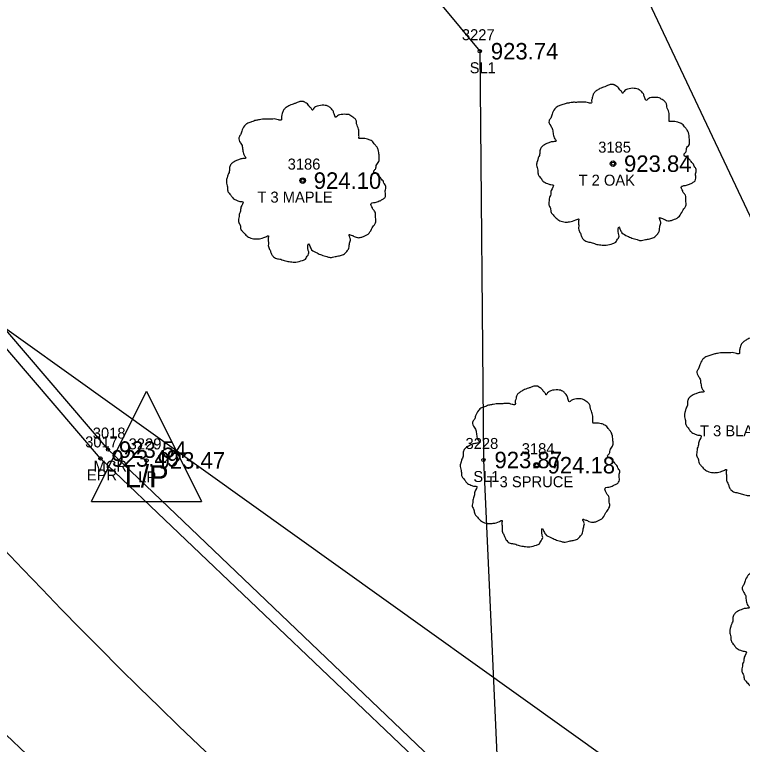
# Model space of a CAD drawing. Extents: x 1575382 to 1578175, y 1099175 to 1101955.
# Drawn here: x 1576931 to 1576997.2, y 1100870.5 to 1100936.8 of the extents above; entities that cross this region are included whole.
import ezdxf

# ---------------------------------------------------------------- set-up
doc = ezdxf.new("R2010")
doc.units = 0
for name, color, linetype in [('RD_EX_Conc', 7, 'Continuous'), ('RD_EX_Conc_txCode', 7, 'Continuous'), ('RD_EX_Road', 7, 'Continuous'), ('RD_EX_Road_txCode', 7, 'Continuous'), ('RD_EX_TX_Conc_ELEV', 7, 'Continuous'), ('RD_EX_TX_Road_ELEV', 7, 'Continuous'), ('RD_EX_TX_UT_ELEV', 7, 'Continuous'), ('RD_EX_TX_VEG_ELEV', 7, 'Continuous'), ('RD_EX_UT', 7, 'Continuous'), ('RD_EX_UT_txCode', 7, 'Continuous'), ('RD_EX_VEG', 7, 'Continuous'), ('RD_EX_VEG_txCode', 7, 'Continuous'), ('RD_HC_Cl', 7, 'Continuous'), ('RD_SMD_Locator', 7, 'Continuous')]:
    doc.layers.add(name, color=color, linetype=linetype)

msp = doc.modelspace()

# ---------------------------------------------------------------- linework, layer by layer
at = {"layer": 'RD_EX_Conc'}
msp.add_lwpolyline([(1577061.066, 1100806.234), (1577014.096, 1100833.352), (1576975.058, 1100863.303), (1576939.512, 1100897.242), (1576908.218, 1100933.822), (1576881.099, 1100974.578), (1576859.041, 1101017.292), (1576841.041, 1101063.527), (1576828.933, 1101110.765), (1576816.791, 1101158.901)], dxfattribs=at)
at = {"layer": 'RD_EX_Road'}
for points in [[(1577060.606, 1100805.432), (1577013.537, 1100832.507), (1576974.41, 1100862.521), (1576938.821, 1100896.441), (1576907.275, 1100933.28), (1576880.287, 1100973.975), (1576858.202, 1101016.828), (1576840.123, 1101063.131), (1576827.927, 1101110.583), (1576815.842, 1101158.489)], [(1576898.125, 1100449.597), (1576900.298, 1100453.323), (1576908.44, 1100470.191), (1576911.626, 1100476.811), (1576915.143, 1100482.86), (1576932.491, 1100514.031), (1576964.319, 1100571.231), (1576981.085, 1100601.291), (1577005.143, 1100644.548), (1577029.514, 1100688.699), (1577055.929, 1100735.941), (1577058.213, 1100744.654), (1577059.154, 1100754.07), (1577057.45, 1100760.722), (1577053.131, 1100767.877), (1577044.533, 1100776.687), (1577044.533, 1100776.687), (1577000.541, 1100813.123), (1576959.676, 1100843.401), (1576921.642, 1100879.474), (1576887.689, 1100919.798), (1576859.542, 1100961.835), (1576835.397, 1101008.919), (1576817.257, 1101055.711)]]:
    msp.add_lwpolyline(points, dxfattribs=at)
at = {"layer": 'RD_EX_UT'}
for p, q in [((1576938.018, 1100892.538), (1576943.018, 1100902.538)), ((1576943.018, 1100902.538), (1576948.018, 1100892.538)), ((1576938.018, 1100892.538), (1576948.018, 1100892.538))]:
    msp.add_line(p, q, dxfattribs=at)
msp.add_lwpolyline([(1576697.982, 1101074.318), (1577079.486, 1100801.524), (1576931.929, 1100529.296), (1577183.503, 1100413.666)], dxfattribs=at)
at = {"layer": 'RD_EX_VEG'}
for points in [[(1576842.661, 1101165.203), (1576856.324, 1101117.296), (1576901.07, 1101050.702), (1576926.345, 1101005.763), (1576957.585, 1100975.469), (1576985.787, 1100943.994), (1577005.951, 1100901.315), (1577049.501, 1100868.209), (1577075.374, 1100845.032), (1577056.225, 1100809.989)], [(1576823.907, 1101161.244), (1576835.181, 1101111.009), (1576847.368, 1101072.746), (1576888.665, 1101041.707), (1576913.762, 1100995.867), (1576945.147, 1100967.302), (1576973.299, 1100933.425), (1576973.63, 1100896.298), (1576975.024, 1100865.506), (1577014.084, 1100835.799), (1577056.225, 1100809.989)]]:
    msp.add_lwpolyline(points, dxfattribs=at)
for centre, radius in [((1576985.404, 1100923.212), 0.25), ((1576985.391, 1100923.193), 0.0001), ((1576957.207, 1100921.676), 0.25), ((1576957.195, 1100921.657), 0.0001), ((1576978.456, 1100895.823), 0.25), ((1576978.443, 1100895.804), 0.0001)]:
    msp.add_circle(centre, radius, dxfattribs=at)
for points in [[(1576985.536, 1100930.379), (1576985.236, 1100930.404), (1576984.911, 1100930.304), (1576984.661, 1100930.204), (1576984.436, 1100930.129), (1576984.212, 1100930.029), (1576983.912, 1100929.854), (1576983.687, 1100929.654), (1576983.562, 1100929.404), (1576983.512, 1100929.179), (1576983.462, 1100928.905), (1576983.462, 1100928.73), (1576983.337, 1100928.705), (1576983.187, 1100928.73), (1576982.937, 1100928.805), (1576982.687, 1100928.805), (1576982.437, 1100928.805), (1576982.087, 1100928.78), (1576981.738, 1100928.78), (1576981.463, 1100928.73), (1576981.138, 1100928.68), (1576980.763, 1100928.555), (1576980.413, 1100928.43), (1576980.113, 1100928.18), (1576979.863, 1100927.705), (1576979.738, 1100927.355), (1576979.589, 1100927.105), (1576979.738, 1100926.656), (1576979.913, 1100926.306), (1576979.938, 1100926.106), (1576980.013, 1100925.681), (1576980.113, 1100925.456), (1576980.238, 1100925.256), (1576980.163, 1100925.231), (1576979.788, 1100925.181), (1576979.489, 1100925.081), (1576979.064, 1100924.856), (1576978.839, 1100924.631), (1576978.739, 1100924.307), (1576978.714, 1100923.957), (1576978.614, 1100923.757), (1576978.539, 1100923.482), (1576978.514, 1100923.407), (1576978.464, 1100923.082), (1576978.564, 1100922.632), (1576978.589, 1100922.282), (1576978.714, 1100922.058), (1576978.864, 1100921.883), (1576979.039, 1100921.633), (1576979.439, 1100921.408), (1576979.763, 1100921.308), (1576979.963, 1100921.283), (1576979.788, 1100920.783), (1576979.738, 1100920.433), (1576979.614, 1100920.033), (1576979.614, 1100919.959), (1576979.564, 1100919.484), (1576979.713, 1100919.159), (1576979.788, 1100918.784), (1576979.963, 1100918.559), (1576980.238, 1100918.259), (1576980.563, 1100918.034), (1576981.063, 1100917.909), (1576981.463, 1100917.934), (1576982.038, 1100918.109), (1576982.287, 1100918.184), (1576982.262, 1100918.009), (1576982.287, 1100917.634), (1576982.287, 1100917.21), (1576982.437, 1100916.885), (1576982.537, 1100916.61), (1576982.687, 1100916.36), (1576983.012, 1100916.135), (1576983.412, 1100916.06), (1576983.837, 1100915.91), (1576984.287, 1100915.835), (1576984.786, 1100915.81), (1576985.386, 1100915.96), (1576985.661, 1100916.085), (1576985.761, 1100916.26), (1576985.961, 1100916.635), (1576985.911, 1100916.86), (1576985.936, 1100917.46), (1576986.036, 1100917.285), (1576986.211, 1100916.935), (1576986.71, 1100916.635), (1576987.11, 1100916.46), (1576987.585, 1100916.31), (1576987.885, 1100916.235), (1576988.36, 1100916.31), (1576988.735, 1100916.385), (1576989.109, 1100916.51), (1576989.409, 1100916.785), (1576989.584, 1100917.06), (1576989.634, 1100917.335), (1576989.709, 1100917.709), (1576989.759, 1100917.884)], [(1576989.759, 1100917.884), (1576989.684, 1100918.059), (1576989.634, 1100918.309), (1576989.709, 1100918.284), (1576989.884, 1100918.234), (1576990.159, 1100918.109), (1576990.384, 1100918.034), (1576990.709, 1100918.059), (1576990.984, 1100918.159), (1576991.433, 1100918.434), (1576991.708, 1100918.909), (1576991.983, 1100919.309), (1576992.058, 1100919.634), (1576992.008, 1100919.859), (1576991.983, 1100920.358), (1576991.783, 1100920.608), (1576991.733, 1100920.733), (1576991.633, 1100921.133), (1576991.708, 1100921.183), (1576991.983, 1100921.233), (1576992.358, 1100921.358), (1576992.633, 1100921.483), (1576992.858, 1100921.658), (1576992.933, 1100921.883), (1576992.908, 1100922.282), (1576992.958, 1100922.682), (1576992.883, 1100922.832), (1576992.783, 1100922.982), (1576992.708, 1100923.182), (1576992.558, 1100923.332), (1576992.458, 1100923.482), (1576992.358, 1100923.582), (1576992.233, 1100923.732), (1576992.058, 1100923.857), (1576991.908, 1100923.907), (1576991.858, 1100924.057), (1576992.008, 1100924.257), (1576992.058, 1100924.357), (1576992.083, 1100924.581), (1576992.308, 1100924.931), (1576992.358, 1100925.331), (1576992.308, 1100925.756), (1576992.258, 1100926.031), (1576992.108, 1100926.306), (1576991.908, 1100926.556), (1576991.783, 1100926.731), (1576991.608, 1100926.855), (1576991.283, 1100926.98), (1576991.034, 1100927.03), (1576990.684, 1100927.03), (1576990.484, 1100927.08), (1576990.509, 1100927.13), (1576990.509, 1100927.28), (1576990.509, 1100927.555), (1576990.434, 1100928.005), (1576990.284, 1100928.505), (1576990.284, 1100928.53), (1576990.184, 1100928.78), (1576989.959, 1100928.98), (1576989.784, 1100929.079), (1576989.584, 1100929.204), (1576989.334, 1100929.229), (1576989.034, 1100929.229), (1576988.76, 1100929.179), (1576988.56, 1100929.079), (1576988.385, 1100928.955), (1576988.31, 1100929.104), (1576988.21, 1100929.404), (1576988.16, 1100929.554), (1576988.01, 1100929.729), (1576987.785, 1100929.929), (1576987.335, 1100930.054), (1576986.71, 1100929.979), (1576986.411, 1100929.779), (1576986.261, 1100929.604), (1576986.211, 1100929.729), (1576986.011, 1100929.929), (1576985.911, 1100930.104), (1576985.736, 1100930.229), (1576985.586, 1100930.329), (1576985.486, 1100930.379)], [(1576957.339, 1100928.843), (1576957.039, 1100928.868), (1576956.714, 1100928.768), (1576956.464, 1100928.668), (1576956.24, 1100928.593), (1576956.015, 1100928.493), (1576955.715, 1100928.318), (1576955.49, 1100928.118), (1576955.365, 1100927.868), (1576955.315, 1100927.643), (1576955.265, 1100927.368), (1576955.265, 1100927.193), (1576955.14, 1100927.168), (1576954.99, 1100927.193), (1576954.74, 1100927.268), (1576954.49, 1100927.268), (1576954.24, 1100927.268), (1576953.891, 1100927.243), (1576953.541, 1100927.243), (1576953.266, 1100927.193), (1576952.941, 1100927.144), (1576952.566, 1100927.019), (1576952.216, 1100926.894), (1576951.916, 1100926.644), (1576951.667, 1100926.169), (1576951.542, 1100925.819), (1576951.392, 1100925.569), (1576951.542, 1100925.119), (1576951.717, 1100924.769), (1576951.741, 1100924.57), (1576951.816, 1100924.145), (1576951.916, 1100923.92), (1576952.041, 1100923.72), (1576951.966, 1100923.695), (1576951.592, 1100923.645), (1576951.292, 1100923.545), (1576950.867, 1100923.32), (1576950.642, 1100923.095), (1576950.542, 1100922.77), (1576950.517, 1100922.421), (1576950.417, 1100922.221), (1576950.342, 1100921.946), (1576950.317, 1100921.871), (1576950.267, 1100921.546), (1576950.367, 1100921.096), (1576950.392, 1100920.746), (1576950.517, 1100920.521), (1576950.667, 1100920.346), (1576950.842, 1100920.097), (1576951.242, 1100919.872), (1576951.567, 1100919.772), (1576951.766, 1100919.747), (1576951.592, 1100919.247), (1576951.542, 1100918.897), (1576951.417, 1100918.497), (1576951.417, 1100918.422), (1576951.367, 1100917.948), (1576951.517, 1100917.623), (1576951.592, 1100917.248), (1576951.766, 1100917.023), (1576952.041, 1100916.723), (1576952.366, 1100916.498), (1576952.866, 1100916.373), (1576953.266, 1100916.398), (1576953.841, 1100916.573), (1576954.09, 1100916.648), (1576954.065, 1100916.473), (1576954.09, 1100916.098), (1576954.09, 1100915.674), (1576954.24, 1100915.349), (1576954.34, 1100915.074), (1576954.49, 1100914.824), (1576954.815, 1100914.599), (1576955.215, 1100914.524), (1576955.64, 1100914.374), (1576956.09, 1100914.299), (1576956.589, 1100914.274), (1576957.189, 1100914.424), (1576957.464, 1100914.549), (1576957.564, 1100914.724), (1576957.764, 1100915.099), (1576957.714, 1100915.324), (1576957.739, 1100915.923), (1576957.839, 1100915.748), (1576958.014, 1100915.399), (1576958.514, 1100915.099), (1576958.913, 1100914.924), (1576959.388, 1100914.774), (1576959.688, 1100914.699), (1576960.163, 1100914.774), (1576960.538, 1100914.849), (1576960.912, 1100914.974), (1576961.212, 1100915.249), (1576961.387, 1100915.524), (1576961.437, 1100915.798), (1576961.512, 1100916.173), (1576961.562, 1100916.348)], [(1576961.562, 1100916.348), (1576961.487, 1100916.523), (1576961.437, 1100916.773), (1576961.512, 1100916.748), (1576961.687, 1100916.698), (1576961.962, 1100916.573), (1576962.187, 1100916.498), (1576962.512, 1100916.523), (1576962.787, 1100916.623), (1576963.236, 1100916.898), (1576963.511, 1100917.373), (1576963.786, 1100917.773), (1576963.861, 1100918.097), (1576963.811, 1100918.322), (1576963.786, 1100918.822), (1576963.586, 1100919.072), (1576963.536, 1100919.197), (1576963.436, 1100919.597), (1576963.511, 1100919.647), (1576963.786, 1100919.697), (1576964.161, 1100919.822), (1576964.436, 1100919.947), (1576964.661, 1100920.122), (1576964.736, 1100920.346), (1576964.711, 1100920.746), (1576964.761, 1100921.146), (1576964.686, 1100921.296), (1576964.586, 1100921.446), (1576964.511, 1100921.646), (1576964.361, 1100921.796), (1576964.261, 1100921.946), (1576964.161, 1100922.046), (1576964.036, 1100922.196), (1576963.861, 1100922.321), (1576963.711, 1100922.371), (1576963.661, 1100922.52), (1576963.811, 1100922.72), (1576963.861, 1100922.82), (1576963.886, 1100923.045), (1576964.111, 1100923.395), (1576964.161, 1100923.795), (1576964.111, 1100924.22), (1576964.061, 1100924.495), (1576963.911, 1100924.769), (1576963.711, 1100925.019), (1576963.586, 1100925.194), (1576963.411, 1100925.319), (1576963.087, 1100925.444), (1576962.837, 1100925.494), (1576962.487, 1100925.494), (1576962.287, 1100925.544), (1576962.312, 1100925.594), (1576962.312, 1100925.744), (1576962.312, 1100926.019), (1576962.237, 1100926.469), (1576962.087, 1100926.969), (1576962.087, 1100926.994), (1576961.987, 1100927.243), (1576961.762, 1100927.443), (1576961.587, 1100927.543), (1576961.387, 1100927.668), (1576961.137, 1100927.693), (1576960.838, 1100927.693), (1576960.563, 1100927.643), (1576960.363, 1100927.543), (1576960.188, 1100927.418), (1576960.113, 1100927.568), (1576960.013, 1100927.868), (1576959.963, 1100928.018), (1576959.813, 1100928.193), (1576959.588, 1100928.393), (1576959.138, 1100928.518), (1576958.514, 1100928.443), (1576958.214, 1100928.243), (1576958.064, 1100928.068), (1576958.014, 1100928.193), (1576957.814, 1100928.393), (1576957.714, 1100928.568), (1576957.539, 1100928.693), (1576957.389, 1100928.793), (1576957.289, 1100928.843)], [(1576998.964, 1100907.617), (1576998.664, 1100907.642), (1576998.34, 1100907.542), (1576998.09, 1100907.442), (1576997.865, 1100907.367), (1576997.64, 1100907.267), (1576997.34, 1100907.092), (1576997.115, 1100906.892), (1576996.99, 1100906.642), (1576996.94, 1100906.417), (1576996.89, 1100906.143), (1576996.89, 1100905.968), (1576996.765, 1100905.943), (1576996.615, 1100905.968), (1576996.365, 1100906.043), (1576996.116, 1100906.043), (1576995.866, 1100906.043), (1576995.516, 1100906.018), (1576995.166, 1100906.018), (1576994.891, 1100905.968), (1576994.566, 1100905.918), (1576994.191, 1100905.793), (1576993.842, 1100905.668), (1576993.542, 1100905.418), (1576993.292, 1100904.943), (1576993.167, 1100904.593), (1576993.017, 1100904.343), (1576993.167, 1100903.894), (1576993.342, 1100903.544), (1576993.367, 1100903.344), (1576993.442, 1100902.919), (1576993.542, 1100902.694), (1576993.667, 1100902.494), (1576993.592, 1100902.469), (1576993.217, 1100902.419), (1576992.917, 1100902.319), (1576992.492, 1100902.094), (1576992.267, 1100901.869), (1576992.167, 1100901.545), (1576992.142, 1100901.195), (1576992.042, 1100900.995), (1576991.967, 1100900.72), (1576991.942, 1100900.645), (1576991.892, 1100900.32), (1576991.992, 1100899.87), (1576992.017, 1100899.52), (1576992.142, 1100899.296), (1576992.292, 1100899.121), (1576992.467, 1100898.871), (1576992.867, 1100898.646), (1576993.192, 1100898.546), (1576993.392, 1100898.521), (1576993.217, 1100898.021), (1576993.167, 1100897.671), (1576993.042, 1100897.271), (1576993.042, 1100897.197), (1576992.992, 1100896.722), (1576993.142, 1100896.397), (1576993.217, 1100896.022), (1576993.392, 1100895.797), (1576993.667, 1100895.497), (1576993.991, 1100895.272), (1576994.491, 1100895.147), (1576994.891, 1100895.172), (1576995.466, 1100895.347), (1576995.716, 1100895.422), (1576995.691, 1100895.247), (1576995.716, 1100894.872), (1576995.716, 1100894.448), (1576995.866, 1100894.123), (1576995.966, 1100893.848), (1576996.116, 1100893.598), (1576996.44, 1100893.373), (1576996.84, 1100893.298), (1576997.265, 1100893.148), (1576997.715, 1100893.073), (1576998.215, 1100893.048), (1576998.814, 1100893.198), (1576999.089, 1100893.323), (1576999.189, 1100893.498), (1576999.389, 1100893.873), (1576999.339, 1100894.098), (1576999.364, 1100894.698), (1576999.464, 1100894.523), (1576999.639, 1100894.173), (1577000.139, 1100893.873), (1577000.539, 1100893.698), (1577001.013, 1100893.548), (1577001.313, 1100893.473), (1577001.788, 1100893.548), (1577002.163, 1100893.623), (1577002.538, 1100893.748), (1577002.838, 1100894.023), (1577003.013, 1100894.298), (1577003.063, 1100894.573), (1577003.137, 1100894.947), (1577003.187, 1100895.122)], [(1576978.588, 1100902.99), (1576978.288, 1100903.015), (1576977.963, 1100902.915), (1576977.713, 1100902.815), (1576977.488, 1100902.74), (1576977.263, 1100902.64), (1576976.963, 1100902.466), (1576976.738, 1100902.266), (1576976.613, 1100902.016), (1576976.563, 1100901.791), (1576976.513, 1100901.516), (1576976.513, 1100901.341), (1576976.389, 1100901.316), (1576976.239, 1100901.341), (1576975.989, 1100901.416), (1576975.739, 1100901.416), (1576975.489, 1100901.416), (1576975.139, 1100901.391), (1576974.789, 1100901.391), (1576974.514, 1100901.341), (1576974.189, 1100901.291), (1576973.815, 1100901.166), (1576973.465, 1100901.041), (1576973.165, 1100900.791), (1576972.915, 1100900.316), (1576972.79, 1100899.967), (1576972.64, 1100899.717), (1576972.79, 1100899.267), (1576972.965, 1100898.917), (1576972.99, 1100898.717), (1576973.065, 1100898.292), (1576973.165, 1100898.067), (1576973.29, 1100897.867), (1576973.215, 1100897.843), (1576972.84, 1100897.793), (1576972.54, 1100897.693), (1576972.115, 1100897.468), (1576971.89, 1100897.243), (1576971.79, 1100896.918), (1576971.766, 1100896.568), (1576971.666, 1100896.368), (1576971.591, 1100896.093), (1576971.566, 1100896.018), (1576971.516, 1100895.693), (1576971.616, 1100895.244), (1576971.641, 1100894.894), (1576971.766, 1100894.669), (1576971.915, 1100894.494), (1576972.09, 1100894.244), (1576972.49, 1100894.019), (1576972.815, 1100893.919), (1576973.015, 1100893.894), (1576972.84, 1100893.394), (1576972.79, 1100893.045), (1576972.665, 1100892.645), (1576972.665, 1100892.57), (1576972.615, 1100892.095), (1576972.765, 1100891.77), (1576972.84, 1100891.395), (1576973.015, 1100891.17), (1576973.29, 1100890.871), (1576973.615, 1100890.646), (1576974.115, 1100890.521), (1576974.514, 1100890.546), (1576975.089, 1100890.721), (1576975.339, 1100890.796), (1576975.314, 1100890.621), (1576975.339, 1100890.246), (1576975.339, 1100889.821), (1576975.489, 1100889.496), (1576975.589, 1100889.221), (1576975.739, 1100888.971), (1576976.064, 1100888.747), (1576976.463, 1100888.672), (1576976.888, 1100888.522), (1576977.338, 1100888.447), (1576977.838, 1100888.422), (1576978.438, 1100888.572), (1576978.712, 1100888.697), (1576978.812, 1100888.871), (1576979.012, 1100889.246), (1576978.962, 1100889.471), (1576978.987, 1100890.071), (1576979.087, 1100889.896), (1576979.262, 1100889.546), (1576979.762, 1100889.246), (1576980.162, 1100889.071), (1576980.637, 1100888.921), (1576980.937, 1100888.846), (1576981.411, 1100888.921), (1576981.786, 1100888.996), (1576982.161, 1100889.121), (1576982.461, 1100889.396), (1576982.636, 1100889.671), (1576982.686, 1100889.946), (1576982.761, 1100890.321), (1576982.811, 1100890.496)], [(1576982.811, 1100890.496), (1576982.736, 1100890.671), (1576982.686, 1100890.921), (1576982.761, 1100890.896), (1576982.936, 1100890.846), (1576983.211, 1100890.721), (1576983.435, 1100890.646), (1576983.76, 1100890.671), (1576984.035, 1100890.771), (1576984.485, 1100891.046), (1576984.76, 1100891.52), (1576985.035, 1100891.92), (1576985.11, 1100892.245), (1576985.06, 1100892.47), (1576985.035, 1100892.97), (1576984.835, 1100893.22), (1576984.785, 1100893.344), (1576984.685, 1100893.744), (1576984.76, 1100893.794), (1576985.035, 1100893.844), (1576985.41, 1100893.969), (1576985.684, 1100894.094), (1576985.909, 1100894.269), (1576985.984, 1100894.494), (1576985.959, 1100894.894), (1576986.009, 1100895.294), (1576985.934, 1100895.444), (1576985.834, 1100895.593), (1576985.759, 1100895.793), (1576985.609, 1100895.943), (1576985.51, 1100896.093), (1576985.41, 1100896.193), (1576985.285, 1100896.343), (1576985.11, 1100896.468), (1576984.96, 1100896.518), (1576984.91, 1100896.668), (1576985.06, 1100896.868), (1576985.11, 1100896.968), (1576985.135, 1100897.193), (1576985.36, 1100897.543), (1576985.41, 1100897.942), (1576985.36, 1100898.367), (1576985.31, 1100898.642), (1576985.16, 1100898.917), (1576984.96, 1100899.167), (1576984.835, 1100899.342), (1576984.66, 1100899.467), (1576984.335, 1100899.592), (1576984.085, 1100899.642), (1576983.735, 1100899.642), (1576983.535, 1100899.692), (1576983.56, 1100899.742), (1576983.56, 1100899.892), (1576983.56, 1100900.167), (1576983.485, 1100900.616), (1576983.335, 1100901.116), (1576983.335, 1100901.141), (1576983.235, 1100901.391), (1576983.011, 1100901.591), (1576982.836, 1100901.691), (1576982.636, 1100901.816), (1576982.386, 1100901.841), (1576982.086, 1100901.841), (1576981.811, 1100901.791), (1576981.611, 1100901.691), (1576981.436, 1100901.566), (1576981.361, 1100901.716), (1576981.261, 1100902.016), (1576981.211, 1100902.166), (1576981.061, 1100902.341), (1576980.837, 1100902.54), (1576980.387, 1100902.665), (1576979.762, 1100902.59), (1576979.462, 1100902.391), (1576979.312, 1100902.216), (1576979.262, 1100902.341), (1576979.062, 1100902.54), (1576978.962, 1100902.715), (1576978.787, 1100902.84), (1576978.638, 1100902.94), (1576978.538, 1100902.99)], [(1577003.08, 1100887.991), (1577002.78, 1100888.016), (1577002.455, 1100887.916), (1577002.206, 1100887.816), (1577001.981, 1100887.741), (1577001.756, 1100887.641), (1577001.456, 1100887.467), (1577001.231, 1100887.267), (1577001.106, 1100887.017), (1577001.056, 1100886.792), (1577001.006, 1100886.517), (1577001.006, 1100886.342), (1577000.881, 1100886.317), (1577000.731, 1100886.342), (1577000.481, 1100886.417), (1577000.231, 1100886.417), (1576999.981, 1100886.417), (1576999.632, 1100886.392), (1576999.282, 1100886.392), (1576999.007, 1100886.342), (1576998.682, 1100886.292), (1576998.307, 1100886.167), (1576997.957, 1100886.042), (1576997.658, 1100885.792), (1576997.408, 1100885.318), (1576997.283, 1100884.968), (1576997.133, 1100884.718), (1576997.283, 1100884.268), (1576997.458, 1100883.918), (1576997.483, 1100883.718), (1576997.558, 1100883.293), (1576997.658, 1100883.069), (1576997.782, 1100882.869), (1576997.708, 1100882.844), (1576997.333, 1100882.794), (1576997.033, 1100882.694), (1576996.608, 1100882.469), (1576996.383, 1100882.244), (1576996.283, 1100881.919), (1576996.258, 1100881.569), (1576996.158, 1100881.369), (1576996.083, 1100881.094), (1576996.058, 1100881.019), (1576996.008, 1100880.695), (1576996.108, 1100880.245), (1576996.133, 1100879.895), (1576996.258, 1100879.67), (1576996.408, 1100879.495), (1576996.583, 1100879.245), (1576996.983, 1100879.02), (1576997.308, 1100878.92), (1576997.508, 1100878.895), (1576997.333, 1100878.396), (1576997.283, 1100878.046), (1576997.158, 1100877.646), (1576997.158, 1100877.571), (1576997.108, 1100877.096), (1576997.258, 1100876.771), (1576997.333, 1100876.396), (1576997.508, 1100876.172), (1576997.782, 1100875.872), (1576998.107, 1100875.647), (1576998.607, 1100875.522), (1576999.007, 1100875.547), (1576999.582, 1100875.722), (1576999.832, 1100875.797), (1576999.807, 1100875.622), (1576999.832, 1100875.247), (1576999.832, 1100874.822), (1576999.981, 1100874.497), (1577000.081, 1100874.222), (1577000.231, 1100873.972), (1577000.556, 1100873.748), (1577000.956, 1100873.673), (1577001.381, 1100873.523), (1577001.831, 1100873.448), (1577002.33, 1100873.423), (1577002.93, 1100873.573), (1577003.205, 1100873.698), (1577003.305, 1100873.873), (1577003.505, 1100874.247), (1577003.455, 1100874.472), (1577003.48, 1100875.072), (1577003.58, 1100874.897), (1577003.755, 1100874.547), (1577004.255, 1100874.247), (1577004.654, 1100874.072), (1577005.129, 1100873.922), (1577005.429, 1100873.848), (1577005.904, 1100873.922), (1577006.279, 1100873.997), (1577006.654, 1100874.122), (1577006.953, 1100874.397), (1577007.128, 1100874.672), (1577007.178, 1100874.947), (1577007.253, 1100875.322), (1577007.303, 1100875.497)]]:
    msp.add_spline(points, degree=3, dxfattribs=at)
at = {"layer": 'RD_HC_Cl'}
msp.add_arc((1577257.909, 1101196.452), 450, 194.10128, 235.13175, dxfattribs=at)
at = {"layer": 'RD_SMD_Locator'}
for centre in [(1576973.299, 1100933.425), (1576985.404, 1100923.212), (1576957.207, 1100921.675), (1576939.512, 1100897.242), (1576938.821, 1100896.441), (1576943.018, 1100896.262), (1576973.63, 1100896.298), (1576978.456, 1100895.823)]:
    msp.add_circle(centre, 0.15, dxfattribs=at)

# ---------------------------------------------------------------- texts
at = {"layer": 'RD_EX_Conc_txCode'}
for s, p in [('3018', (1576938.126, 1100898.242)), ('MCR', (1576938.197, 1100895.242))]:
    msp.add_text(s, height=1, dxfattribs=at).set_placement(p)
at = {"layer": 'RD_EX_Road_txCode'}
for s, p in [('3017', (1576937.435, 1100897.441)), ('EPR', (1576937.592, 1100894.441))]:
    msp.add_text(s, height=1, dxfattribs=at).set_placement(p)
at = {"layer": 'RD_EX_TX_Conc_ELEV'}
msp.add_text('923.54', height=1.5, dxfattribs=at).set_placement((1576940.512, 1100896.492))
at = {"layer": 'RD_EX_TX_Road_ELEV'}
msp.add_text('923.49', height=1.5, dxfattribs=at).set_placement((1576939.821, 1100895.691))
at = {"layer": 'RD_EX_TX_UT_ELEV'}
msp.add_text('923.47', height=1.5, dxfattribs=at).set_placement((1576944.018, 1100895.512))
at = {"layer": 'RD_EX_TX_VEG_ELEV'}
for s, p in [('923.74', (1576974.299, 1100932.675)), ('923.84', (1576986.404, 1100922.462)), ('924.10', (1576958.207, 1100920.925)), ('923.87', (1576974.63, 1100895.548)), ('924.18', (1576979.456, 1100895.073))]:
    msp.add_text(s, height=1.5, dxfattribs=at).set_placement(p)
at = {"layer": 'RD_EX_UT'}
msp.add_text('L/P', height=2, dxfattribs=at).set_placement((1576941.009, 1100893.819))
at = {"layer": 'RD_EX_UT_txCode'}
for s, p in [('3229', (1576941.388, 1100897.262)), ('LP', (1576942.262, 1100894.262))]:
    msp.add_text(s, height=1, dxfattribs=at).set_placement(p)
at = {"layer": 'RD_EX_VEG_txCode'}
for s, p in [('3227', (1576971.669, 1100934.425)), ('SL1', (1576972.377, 1100931.425)), ('3185', (1576984.058, 1100924.212)), ('3186', (1576955.837, 1100922.675)), ('T 2 OAK', (1576982.27, 1100921.212)), ('T 3 MAPLE', (1576953.085, 1100919.675)), ('T 3 BLACKGUM', (1576993.305, 1100898.45)), ('3228', (1576972, 1100897.298)), ('3184', (1576977.109, 1100896.823)), ('SL1', (1576972.709, 1100894.298)), ('T 3 SPRUCE', (1576973.908, 1100893.823))]:
    msp.add_text(s, height=1, dxfattribs=at).set_placement(p)

doc.saveas('drawing.dxf')
